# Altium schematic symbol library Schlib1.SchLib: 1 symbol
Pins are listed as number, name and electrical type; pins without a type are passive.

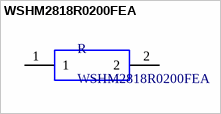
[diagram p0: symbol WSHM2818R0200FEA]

## WSHM2818R0200FEA
designator R
Rezistory ke snímání proudu - SMD .02ohms 7watt 1%; Value: 0.02R; Power: 7W
footprint WSHM2818R0200FEA
pins: 1, 2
